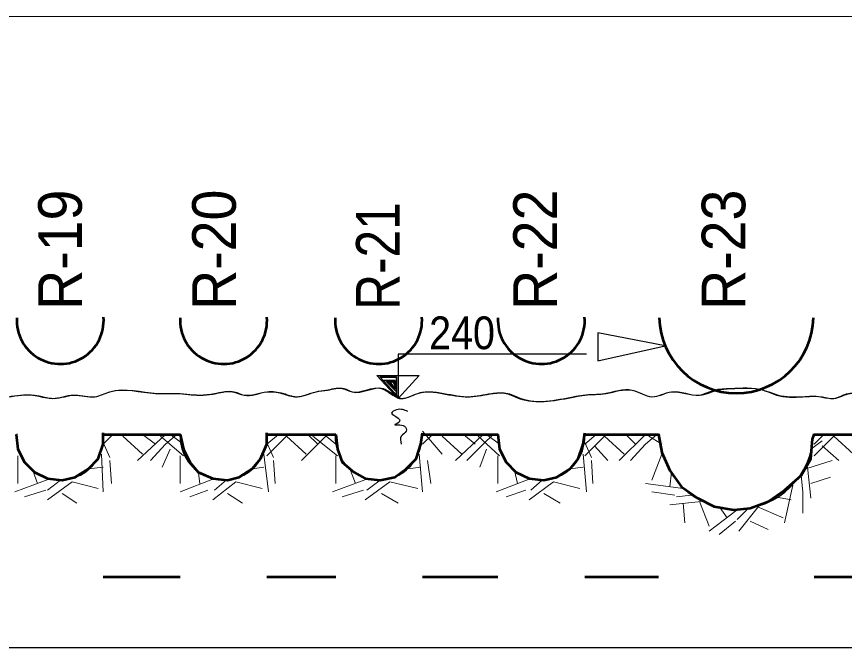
# Model space of a CAD drawing. Extents: x 8426.2 to 8495.4, y 19933.5 to 19963.2.
# Drawn here: x 8468.08 to 8473.14, y 19944.82 to 19948.67 of the extents above; entities that cross this region are included whole.
import ezdxf

# ---------------------------------------------------------------- set-up
doc = ezdxf.new("R2010")
doc.units = 0
doc.header["$LTSCALE"] = 0.11
for name, color, linetype, lineweight in [('1', 7, 'Continuous', 35), ('2', 7, 'Continuous', 13), ('3', 7, 'Continuous', 25)]:
    doc.layers.add(name, color=color, linetype=linetype, lineweight=lineweight)

msp = doc.modelspace()

# ---------------------------------------------------------------- linework, layer by layer
at = {"layer": '1', "lineweight": 25}
msp.add_lwpolyline([(8471.56, 19946.61), (8470.41, 19946.61), (8470.41, 19946.34), (8470.28, 19946.48), (8470.54, 19946.48), (8470.41, 19946.34)], dxfattribs=at)
at = {"layer": '1'}
for points in [[(8470.41, 19946.35), (8470.3, 19946.47), (8470.4, 19946.47), (8470.4, 19946.36), (8470.32, 19946.45), (8470.39, 19946.45), (8470.4, 19946.38), (8470.34, 19946.44), (8470.39, 19946.44), (8470.39, 19946.4), (8470.36, 19946.44)], [(8470.39, 19946.42), (8470.38, 19946.44), (8470.35, 19946.44), (8470.39, 19946.4)]]:
    msp.add_lwpolyline(points, dxfattribs=at)
at = {"layer": '1', "lineweight": 25}
msp.add_spline([(8470.47, 19946.26), (8470.4, 19946.27), (8470.37, 19946.25), (8470.41, 19946.22), (8470.42, 19946.2), (8470.39, 19946.18), (8470.45, 19946.17), (8470.46, 19946.14), (8470.43, 19946.11), (8470.43, 19946.06)], degree=3, dxfattribs=at)
at = {"layer": '2'}
for p, q in [((8470.56, 19946.14), (8470.68, 19946)), ((8468.67, 19946.12), (8468.61, 19946.06)), ((8468.73, 19946.11), (8468.85, 19946)), ((8468.99, 19946.12), (8468.82, 19945.96)), ((8468.85, 19946.12), (8468.93, 19946.06)), ((8469.1, 19945.99), (8468.96, 19946.11)), ((8469.06, 19946.12), (8468.99, 19946.06)), ((8469.1, 19946.06), (8469.02, 19946.12)), ((8469.68, 19946.12), (8469.61, 19946.06)), ((8469.74, 19946.12), (8469.61, 19945.99)), ((8469.73, 19946.11), (8469.85, 19946)), ((8469.98, 19946.12), (8469.82, 19945.96)), ((8469.86, 19946.12), (8469.92, 19946.06)), ((8470.04, 19945.99), (8469.89, 19946.11)), ((8470.03, 19946.06), (8469.96, 19946.12)), ((8470.62, 19946.12), (8470.56, 19946.06)), ((8470.68, 19946.11), (8470.8, 19946)), ((8470.93, 19946.12), (8470.76, 19945.96)), ((8470.81, 19946.12), (8470.88, 19946.06)), ((8471.03, 19945.99), (8470.9, 19946.11)), ((8470.99, 19946.12), (8470.93, 19946.06)), ((8471.03, 19946.06), (8470.95, 19946.12)), ((8471.62, 19946.12), (8471.55, 19946.06)), ((8471.68, 19946.12), (8471.55, 19945.99)), ((8471.67, 19946.11), (8471.79, 19946)), ((8471.92, 19946.12), (8471.76, 19945.96)), ((8471.8, 19946.12), (8471.86, 19946.06)), ((8471.99, 19946.12), (8471.92, 19946.06)), ((8472.02, 19946.06), (8471.94, 19946.11)), ((8473.01, 19946.12), (8472.95, 19946.06)), ((8473.08, 19946.12), (8472.95, 19945.99)), ((8473.07, 19946.11), (8473.19, 19946)), ((8468.61, 19946.07), (8468.65, 19945.98)), ((8468.99, 19946.06), (8468.9, 19945.96)), ((8469.61, 19946.07), (8469.65, 19945.98)), ((8470.93, 19946.06), (8470.83, 19945.96)), ((8471.55, 19946.07), (8471.59, 19945.98)), ((8471.61, 19946.05), (8471.69, 19945.96)), ((8471.92, 19946.06), (8471.83, 19945.96)), ((8472.93, 19946.03), (8473, 19946.08)), ((8473, 19946.05), (8473.1, 19945.96)), ((8468.09, 19945.99), (8468.09, 19945.82)), ((8468.6, 19946), (8468.61, 19945.77)), ((8469.02, 19946.03), (8468.97, 19945.92)), ((8469.08, 19945.99), (8469.08, 19945.82)), ((8469.59, 19946), (8469.62, 19945.77)), ((8470.03, 19945.99), (8470.03, 19945.82)), ((8470.54, 19946), (8470.56, 19945.77)), ((8470.95, 19946.03), (8470.91, 19945.92)), ((8471.02, 19945.99), (8471.02, 19945.82)), ((8471.54, 19946), (8471.56, 19945.77)), ((8472.02, 19946), (8471.96, 19945.84)), ((8468.65, 19945.96), (8468.66, 19945.82)), ((8469.65, 19945.96), (8469.66, 19945.82)), ((8470.59, 19945.96), (8470.61, 19945.82)), ((8471.59, 19945.96), (8471.6, 19945.82)), ((8472.9, 19945.91), (8473.06, 19945.96)), ((8468.18, 19945.9), (8468.21, 19945.82)), ((8468.52, 19945.91), (8468.61, 19945.92)), ((8469.19, 19945.9), (8469.2, 19945.82)), ((8469.52, 19945.91), (8469.59, 19945.92)), ((8470.12, 19945.9), (8470.15, 19945.82)), ((8470.47, 19945.91), (8470.55, 19945.92)), ((8471.12, 19945.9), (8471.14, 19945.82)), ((8471.46, 19945.91), (8471.54, 19945.92)), ((8472.08, 19945.89), (8472.07, 19945.8)), ((8472.91, 19945.92), (8472.93, 19945.73)), ((8468.29, 19945.85), (8468.07, 19945.77)), ((8468.35, 19945.84), (8468.27, 19945.78)), ((8469.29, 19945.85), (8469.08, 19945.77)), ((8469.36, 19945.84), (8469.29, 19945.78)), ((8470.23, 19945.85), (8470.01, 19945.77)), ((8470.3, 19945.84), (8470.22, 19945.78)), ((8471.22, 19945.85), (8471.01, 19945.77)), ((8471.29, 19945.84), (8471.22, 19945.78)), ((8472.87, 19945.87), (8472.88, 19945.77)), ((8472.93, 19945.82), (8473.05, 19945.86)), ((8468.42, 19945.83), (8468.27, 19945.72)), ((8468.42, 19945.83), (8468.58, 19945.79)), ((8469.42, 19945.83), (8469.28, 19945.72)), ((8469.42, 19945.83), (8469.58, 19945.79)), ((8470.36, 19945.83), (8470.21, 19945.72)), ((8470.36, 19945.83), (8470.53, 19945.79)), ((8471.36, 19945.83), (8471.21, 19945.72)), ((8471.36, 19945.83), (8471.52, 19945.79)), ((8472.15, 19945.79), (8471.92, 19945.82)), ((8472.82, 19945.81), (8472.77, 19945.58)), ((8468.26, 19945.78), (8468.13, 19945.74)), ((8468.36, 19945.76), (8468.45, 19945.7)), ((8469.25, 19945.78), (8469.14, 19945.74)), ((8469.37, 19945.76), (8469.46, 19945.7)), ((8470.2, 19945.78), (8470.07, 19945.74)), ((8470.31, 19945.76), (8470.41, 19945.7)), ((8471.19, 19945.78), (8471.07, 19945.74)), ((8471.3, 19945.76), (8471.4, 19945.7)), ((8472.1, 19945.75), (8471.96, 19945.77)), ((8472.2, 19945.75), (8472.11, 19945.74)), ((8472.71, 19945.74), (8472.81, 19945.72)), ((8472.88, 19945.77), (8472.88, 19945.64)), ((8472.26, 19945.71), (8472.07, 19945.69)), ((8472.15, 19945.7), (8472.16, 19945.58)), ((8472.25, 19945.71), (8472.31, 19945.56)), ((8472.48, 19945.66), (8472.31, 19945.53)), ((8472.37, 19945.68), (8472.42, 19945.61)), ((8472.55, 19945.67), (8472.48, 19945.6)), ((8472.61, 19945.68), (8472.49, 19945.53)), ((8472.6, 19945.68), (8472.76, 19945.61)), ((8472.47, 19945.59), (8472.37, 19945.51)), ((8472.56, 19945.59), (8472.67, 19945.54))]:
    msp.add_line(p, q, dxfattribs=at)
at = {"layer": '2', "lineweight": 53}
for p, q in [((8468.61, 19946.12), (8469.08, 19946.12)), ((8469.61, 19946.12), (8470.03, 19946.12)), ((8470.56, 19946.12), (8471.02, 19946.12)), ((8471.55, 19946.12), (8472, 19946.12)), ((8472.95, 19946.12), (8473.42, 19946.12)), ((8468.61, 19945.25), (8469.08, 19945.25)), ((8469.61, 19945.25), (8470.03, 19945.25)), ((8470.56, 19945.25), (8471.02, 19945.25)), ((8471.55, 19945.25), (8472, 19945.25)), ((8472.95, 19945.25), (8473.42, 19945.25))]:
    msp.add_line(p, q, dxfattribs=at)
at = {"layer": '2', "lineweight": 25}
msp.add_lwpolyline([(8472.04, 19946.66), (8471.63, 19946.74), (8471.63, 19946.57)], close=True, dxfattribs=at)
at = {"layer": '2', "lineweight": 53}
for points in [[(8468.08, 19946.12), (8468.09, 19946.03), (8468.13, 19945.95), (8468.19, 19945.89), (8468.27, 19945.85), (8468.36, 19945.84), (8468.44, 19945.86), (8468.52, 19945.91), (8468.58, 19945.97), (8468.61, 19946.06), (8468.61, 19946.13)], [(8469.08, 19946.12), (8469.1, 19946.03), (8469.14, 19945.95), (8469.19, 19945.89), (8469.28, 19945.85), (8469.37, 19945.84), (8469.44, 19945.86), (8469.52, 19945.91), (8469.57, 19945.97), (8469.61, 19946.06), (8469.61, 19946.13)], [(8470.03, 19946.12), (8470.04, 19946.03), (8470.07, 19945.95), (8470.14, 19945.89), (8470.21, 19945.85), (8470.3, 19945.84), (8470.39, 19945.86), (8470.46, 19945.91), (8470.52, 19945.97), (8470.55, 19946.06), (8470.56, 19946.13)], [(8471.02, 19946.12), (8471.03, 19946.03), (8471.07, 19945.95), (8471.13, 19945.89), (8471.21, 19945.85), (8471.3, 19945.84), (8471.38, 19945.86), (8471.46, 19945.91), (8471.51, 19945.97), (8471.54, 19946.06), (8471.55, 19946.13)], [(8472, 19946.12), (8472.02, 19946.01), (8472.07, 19945.9), (8472.14, 19945.8), (8472.24, 19945.73), (8472.34, 19945.68), (8472.46, 19945.66), (8472.56, 19945.67), (8472.67, 19945.71), (8472.77, 19945.78), (8472.87, 19945.87), (8472.93, 19945.97), (8472.94, 19946.09), (8472.95, 19946.12)]]:
    msp.add_lwpolyline(points, dxfattribs=at)
for centre, radius, start, end in [((8468.3481, 19946.815), 0.2652, 176.5407, 4.4698), ((8468.3481, 19946.815), 0.2652, 176.5407, 4.4698), ((8468.3481, 19946.815), 0.2652, 176.5407, 4.4698), ((8469.3454, 19946.815), 0.2652, 176.5407, 4.4698), ((8469.3454, 19946.815), 0.2652, 176.5407, 4.4698), ((8469.3454, 19946.815), 0.2652, 176.5407, 4.4698), ((8470.2914, 19946.815), 0.2652, 176.5407, 4.4698), ((8470.2914, 19946.815), 0.2652, 176.5407, 4.4698), ((8470.2914, 19946.815), 0.2652, 176.5407, 4.4698), ((8471.2848, 19946.815), 0.2652, 176.5407, 4.4698), ((8471.2848, 19946.815), 0.2652, 176.5407, 4.4698), ((8471.2848, 19946.815), 0.2652, 176.5407, 4.4698), ((8472.4752, 19946.843), 0.4714, 181.4616, 358.5384), ((8472.4752, 19946.843), 0.4714, 181.4616, 358.5384), ((8472.4752, 19946.843), 0.4714, 181.4616, 358.5384)]:
    msp.add_arc(centre, radius, start, end, dxfattribs=at)
at = {"layer": '3', "lineweight": 13}
msp.add_line((8431.27, 19948.67), (8493.73, 19948.67), dxfattribs=at)
at = {"layer": '3'}
for p, q in [((8469.08, 19946.12), (8468.61, 19946.12)), ((8470.03, 19946.12), (8469.61, 19946.12)), ((8471.02, 19946.12), (8470.56, 19946.12)), ((8472, 19946.12), (8471.55, 19946.12)), ((8473.42, 19946.12), (8472.95, 19946.12)), ((8431.27, 19944.82), (8493.73, 19944.82))]:
    msp.add_line(p, q, dxfattribs=at)
for centre, radius, start, end in [((8468.3481, 19946.1068), 0.2652, 176.5407, 4.4698), ((8469.3454, 19946.1068), 0.2652, 176.5407, 4.4698), ((8470.2914, 19946.1068), 0.2652, 176.5407, 4.4698), ((8471.2848, 19946.1068), 0.2652, 176.5407, 4.4698), ((8472.4752, 19946.1348), 0.4714, 181.4616, 358.5384)]:
    msp.add_arc(centre, radius, start, end, dxfattribs=at)
for points in [[(8466.81, 19946.36), (8466.93, 19946.35), (8467.1, 19946.31), (8467.24, 19946.34), (8467.4, 19946.31), (8467.52, 19946.36), (8467.62, 19946.38), (8467.69, 19946.35), (8467.86, 19946.39), (8467.92, 19946.36), (8468.03, 19946.35), (8468.19, 19946.36), (8468.31, 19946.34), (8468.44, 19946.36), (8468.56, 19946.35), (8468.65, 19946.38), (8468.94, 19946.37), (8469.06, 19946.37), (8469.22, 19946.36), (8469.3, 19946.37), (8469.41, 19946.38), (8469.47, 19946.36), (8469.61, 19946.38), (8469.71, 19946.37), (8469.79, 19946.35), (8469.91, 19946.38), (8469.98, 19946.39), (8470.08, 19946.4), (8470.13, 19946.38), (8470.32, 19946.4), (8470.43, 19946.34), (8470.53, 19946.37), (8470.6, 19946.38), (8470.69, 19946.37), (8470.85, 19946.35), (8470.99, 19946.37), (8471.08, 19946.37), (8471.16, 19946.34), (8471.49, 19946.35), (8471.55, 19946.36), (8471.68, 19946.37), (8471.84, 19946.39), (8471.96, 19946.35), (8472.08, 19946.38), (8472.25, 19946.36), (8472.36, 19946.39), (8472.44, 19946.4), (8472.64, 19946.39), (8472.73, 19946.36), (8472.88, 19946.35), (8472.99, 19946.35), (8473.07, 19946.34), (8473.17, 19946.37), (8473.24, 19946.37), (8473.33, 19946.37), (8473.44, 19946.37), (8473.57, 19946.38), (8473.71, 19946.39), (8473.8, 19946.37), (8473.92, 19946.37), (8474.03, 19946.37), (8474.1, 19946.37), (8474.14, 19946.37)], [(8466.81, 19946.36), (8466.91, 19946.35), (8467.1, 19946.31), (8467.24, 19946.34), (8467.4, 19946.31), (8467.52, 19946.36), (8467.6, 19946.38), (8467.69, 19946.35), (8467.85, 19946.39), (8467.91, 19946.36), (8468.03, 19946.35), (8468.18, 19946.36), (8468.3, 19946.34), (8468.43, 19946.36), (8468.56, 19946.35), (8468.65, 19946.38), (8468.93, 19946.37), (8469.06, 19946.37), (8469.2, 19946.36), (8469.29, 19946.37), (8469.4, 19946.38), (8469.47, 19946.36), (8469.61, 19946.38), (8469.7, 19946.37), (8469.78, 19946.35), (8469.91, 19946.38), (8469.97, 19946.39), (8470.07, 19946.4), (8470.13, 19946.38), (8470.31, 19946.4), (8470.42, 19946.34), (8470.53, 19946.37), (8470.59, 19946.38), (8470.68, 19946.37), (8470.84, 19946.35), (8470.98, 19946.37), (8471.07, 19946.37), (8471.15, 19946.34), (8471.48, 19946.35), (8471.54, 19946.36), (8471.67, 19946.37), (8471.84, 19946.39), (8471.96, 19946.35), (8472.08, 19946.38), (8472.25, 19946.36), (8472.34, 19946.39), (8472.44, 19946.4), (8472.64, 19946.39), (8472.72, 19946.36), (8472.88, 19946.35), (8472.99, 19946.35), (8473.07, 19946.34), (8473.16, 19946.37), (8473.24, 19946.37), (8473.31, 19946.37), (8473.42, 19946.37), (8473.56, 19946.38), (8473.7, 19946.39), (8473.8, 19946.37), (8473.92, 19946.37), (8474.03, 19946.37), (8474.1, 19946.37), (8474.13, 19946.37)]]:
    msp.add_spline(points, degree=3, dxfattribs=at)

# ---------------------------------------------------------------- texts
at = {"layer": '1'}
for s, width, p in [('R-19', 0.95, (8468.48, 19946.88)), ('R-20', 0.95, (8469.42, 19946.88)), ('R-22', 0.95, (8471.38, 19946.88)), ('R-23', 0.95, (8472.53, 19946.88)), ('R-21', 0.85, (8470.42, 19946.88))]:
    msp.add_text(s, height=0.2665, rotation=90, dxfattribs=dict(at, width=width)).set_placement(p)
at = {"layer": '2', "width": 0.9}
msp.add_text('240', height=0.1999, dxfattribs=at).set_placement((8470.6, 19946.64))

doc.saveas('drawing.dxf')
